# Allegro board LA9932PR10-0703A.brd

Outline 302.59 x 222.15 mm; copper layers: TOP, GND1, IN1, GND2, IN2, IN3, VCC, IN4, GND3, BOTTOM. Coordinates in mm from the lower left corner of the outline.

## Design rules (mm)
net group 12: nets PCH_PCIE_IREF PCH_PCIE_RCOMP
net group CLK-20: nets UIM_CLK UIM_DATA
net group CLK_BUF_BCLK: nets CLK_BUF_BCLK CLK_BUF_BCLK#
net group CLK_CPU_SSC_DPLL: nets CLK_CPU_SSC_DPLL CLK_CPU_SSC_DPLL#
net group CLK_KBD: nets CLK_KBD DAT_KBD
net group CLK_MSE: nets CLK_MSE DAT_MSE
net group CLK_PCIE_MINI1: nets CLK_PCIE_MINI1 CLK_PCIE_MINI1#
net group CLK_TP_SIO: nets CLK_TP_SIO DAT_TP_SIO
net group CPU_SSC_DPLL: nets CPU_SSC_DPLL CPU_SSC_DPLL#
net group CSS_1: nets CSSN_1 CSSP_1
net group DIFFPAIR75: nets M_CLK_DDR0 M_CLK_DDR#0
net group DIFFPAIR76: nets M_CLK_DDR2 M_CLK_DDR#2
net group DIFFPAIR145: nets DMIC0 DMIC_CLK
net group DIFFPAIR157: nets Z4304 Z4305
net group DOCK_DCIN_IS: nets DOCK_DCIN_IS+ DOCK_DCIN_IS-
net group DPC_CA_DET: nets DPC_CA_DET DPC_CA_DET#
net group DPC_DOCK_LANE_N0: nets DPC_DOCK_LANE_N0 DPC_DOCK_LANE_P0
net group DPC_DOCK_LANE_N1: nets DPC_DOCK_LANE_N1 DPC_DOCK_LANE_P1
net group DPC_DOCK_LANE_N2: nets DPC_DOCK_LANE_N2 DPC_DOCK_LANE_P2
net group DPC_DOCK_LANE_N3: nets DPC_DOCK_LANE_N3 DPC_DOCK_LANE_P3
net group DPD_CA_DET: nets DPD_CA_DET DPD_CA_DET#
net group DPD_DOCK_LANE_N0: nets DPD_DOCK_LANE_N0 DPD_DOCK_LANE_P0
net group DPD_DOCK_LANE_N1: nets DPD_DOCK_LANE_N1 DPD_DOCK_LANE_P1
net group DPD_DOCK_LANE_N2: nets DPD_DOCK_LANE_N2 DPD_DOCK_LANE_P2
net group DPD_DOCK_LANE_N3: nets DPD_DOCK_LANE_N3 DPD_DOCK_LANE_P3
net group FDI-SINGLE: nets FDI_CSYNC FDI_INT
net group ISUM: nets ISUMN ISUMP
net group PCH_DDPB_CTRLCLK: nets PCH_DDPB_CTRLCLK PCH_DDPB_CTRLDATA
net group PCIE_PRX_EXPTX_7: nets PCIE_PRX_EXPTX_N7 PCIE_PRX_EXPTX_P7
net group PCIE_PRX_GLANTX_2: nets PCIE_PRX_GLANTX_N2 PCIE_PRX_GLANTX_P2
net group PCIE_PRX_GLANTX_2_C: nets PCIE_PRX_GLANTX_N2_C PCIE_PRX_GLANTX_P2_C
net group PCIE_PRX_MMITX_8: nets PCIE_PRX_MMITX_N8 PCIE_PRX_MMITX_P8
net group PCIE_PRX_MMITX_8_C: nets PCIE_PRX_MMITX_N8_C PCIE_PRX_MMITX_P8_C
net group PCIE_PRX_WLANTX_3: nets PCIE_PRX_WLANTX_N3 PCIE_PRX_WLANTX_P3
net group PCIE_PRX_WPANTX_6: nets PCIE_PRX_WPANTX_N6 PCIE_PRX_WPANTX_P6
net group PCIE_PTX_EXPRX_7: nets PCIE_PTX_EXPRX_N7 PCIE_PTX_EXPRX_P7
net group PCIE_PTX_GLANRX_2: nets PCIE_PTX_GLANRX_N2 PCIE_PTX_GLANRX_P2
net group PCIE_PTX_GLANRX_2_C: nets PCIE_PTX_GLANRX_N2_C PCIE_PTX_GLANRX_P2_C
net group PCIE_PTX_MMIRX_8: nets PCIE_PTX_MMIRX_N8 PCIE_PTX_MMIRX_P8
net group PCIE_PTX_MMIRX_8_C: nets PCIE_PTX_MMIRX_N8_C PCIE_PTX_MMIRX_P8_C
net group PCIE_PTX_WLANRX_3: nets PCIE_PTX_WLANRX_N3 PCIE_PTX_WLANRX_P3
net group PCIE_PTX_WLANRX_3_C: nets PCIE_PTX_WLANRX_N3_C PCIE_PTX_WLANRX_P3_C
net group PCIE_PTX_WPANRX_6: nets PCIE_PTX_WPANRX_N6 PCIE_PTX_WPANRX_P6
net group PCIE_PTX_WPANRX_6_C: nets PCIE_PTX_WPANRX_N6_C PCIE_PTX_WPANRX_P6_C
net group PCIE_SATA_PRX_WANTX_4: nets PCIE_SATA_PRX_WANTX_N4 PCIE_SATA_PRX_WANTX_P4
net group PCIE_SATA_PTX_WANRX_4: nets PCIE_SATA_PTX_WANRX_N4 PCIE_SATA_PTX_WANRX_P4
net group PCIE_SATA_PTX_WANRX_4_C: nets PCIE_SATA_PTX_WANRX_N4_C PCIE_SATA_PTX_WANRX_P4_C
net group PECI-SINGLE: nets PECI_EC PECI_EC_R
net group PEG_CTX_GRX_0: nets PEG_CTX_GRX_N0 PEG_CTX_GRX_P0
net group PEG_CTX_GRX_2: nets PEG_CTX_GRX_N2 PEG_CTX_GRX_P2
net group PEG_CTX_GRX_4: nets PEG_CTX_GRX_N4 PEG_CTX_GRX_P4
net group PEG_CTX_GRX_6: nets PEG_CTX_GRX_N6 PEG_CTX_GRX_P6
net group PEG_CTX_GRX_C_0: nets PEG_CTX_GRX_C_N0 PEG_CTX_GRX_C_P0
net group PEG_CTX_GRX_C_2: nets PEG_CTX_GRX_C_N2 PEG_CTX_GRX_C_P2
net group PEG_CTX_GRX_C_4: nets PEG_CTX_GRX_C_N4 PEG_CTX_GRX_C_P4
net group PEG_CTX_GRX_C_6: nets PEG_CTX_GRX_C_N6 PEG_CTX_GRX_C_P6
net group PSATA_PRX_DTX_0_C: nets PSATA_PRX_DTX_N0_C PSATA_PRX_DTX_P0_C
net group PSATA_PTX_DRX_0_C: nets PSATA_PTX_DRX_N0_C PSATA_PTX_DRX_P0_C
net group RTCRST: nets PCH_RTCRST# SRTCRST#
net group SATA_PRX_DKTX_2: nets SATA_PRX_DKTX_N2 SATA_PRX_DKTX_P2
net group SATA_PRX_DKTX_2_C: nets SATA_PRX_DKTX_N2_C SATA_PRX_DKTX_P2_C
net group SATA_PTX_DKRX_2: nets SATA_PTX_DKRX_N2 SATA_PTX_DKRX_P2
net group SATA_PTX_DKRX_2_C: nets SATA_PTX_DKRX_N2_C SATA_PTX_DKRX_P2_C
net group TMDSB_CPU_CLK: nets TMDSB_CPU_CLK TMDSB_CPU_CLK#
net group TMDSB_CPU_N0: nets TMDSB_CPU_N0 TMDSB_CPU_P0
net group TMDSB_CPU_N1: nets TMDSB_CPU_N1 TMDSB_CPU_P1
net group TMDSB_CPU_N2: nets TMDSB_CPU_N2 TMDSB_CPU_P2
net group TMDSE_CPU_CLK_C: nets TMDSE_CPU_CLK#_C TMDSE_CPU_CLK_C
net group TMDSE_CPU_N0_C: nets TMDSE_CPU_N0_C TMDSE_CPU_P0_C
net group TMDSE_CPU_N1_C: nets TMDSE_CPU_N1_C TMDSE_CPU_P1_C
net group TMDSE_CPU_N2_C: nets TMDSE_CPU_N2_C TMDSE_CPU_P2_C
net group USB3R5: nets USB3RN5 USB3RP5
net group USB3R6: nets USB3RN6 USB3RP6
net group USB3RP5_D+: nets USB3RN5_D- USB3RP5_D+
net group USB3T5: nets USB3TN5 USB3TP5
net group USB3T5_C: nets USB3TN5_C USB3TP5_C
net group USB3T6: nets USB3TN6 USB3TP6
net group USB3TP5_D+: nets USB3TN5_D- USB3TP5_D+
net group USBP6_R_D: nets USBP6_R_D+ USBP6_R_D-
net group USBP13: nets USBP13+ USBP13-
net group USBP13_D: nets USBP13_D+ USBP13_D-
net group VSUM_VGA: nets VSUM+_VGA VSUM-_VGA
net group WCKA0_0: nets WCKA0_0 WCKA0B_0
net group WCKA0_1: nets WCKA0_1 WCKA0B_1
net group WCKA1_0: nets WCKA1_0 WCKA1B_0
net group WCKA1_1: nets WCKA1_1 WCKA1B_1
net group 10: nets PCH_SPI_CS0# PCH_SPI_CS1# PCH_SPI_DIN PCH_SPI_DO PCH_SPI_DO2 PCH_SPI_DO3 SPI_DIN32 SPI_DIN64 SPI_DO32 SPI_DO64 SPI_PCH_CLK SPI_PCH_CS0# SPI_PCH_CS0#_R SPI_PCH_CS1# SPI_PCH_CS1#_R SPI_PCH_DIN SPI_PCH_DO SPI_PCH_DO2 SPI_PCH_DO2_32 SPI_PCH_DO2_64 SPI_PCH_DO3 SPI_PCH_DO3_32 SPI_PCH_DO3_64
net group 15: nets CLK_80H CLK_PCH_14M CLK_PCI_LOOPBACK CLK_PCI_TPM CLK_SIO_14M EC_32KHZ_ECE5048 ICLK_IREF MEC_XTAL1 MEC_XTAL2 PCH_CLK_BIASREF PCI_LOOPBACKOUT PCI_TPM_TCM PCLK_80H PEG_COMP SIO_14M XTAL25_IN XTAL25_IN_R XTAL25_OUT XTALI XTALIN XTALO XTALOUT XTALOUT_R
net group 20: nets +NBDOCK_DC_IN_SS CFG_RCOMP CLK_PCI_5048 CLK_PCI_DOCK CLK_PCI_MEC DMI_IREF DMI_RCOMP FDI_IREF FDI_RCOMP PCH_SPI_CLK PCI_5048 PCI_DOCK PCI_MEC SATA_COMP SATA_IREF SPI_CLK32 SPI_CLK64
net group 25: nets EDP_COMP SM_RCOMP0 SM_RCOMP1 SM_RCOMP2
net group 30: nets CRT_IREF
net group ASYNCHRONOUS-50H: nets CPU_PLTRST# CPU_PLTRST#_R DDR3_DRAMRST#_CPU DDR3_DRAMRST#_R H_CATERR# H_CPUPWRGD H_CPUPWRGD_XDP H_PM_SYNC H_PROCHOT# H_PROCHOT#_R H_THERMTRIP# H_THERMTRIP#_R PCH_JTAG_TCK PCH_JTAG_TDI PCH_JTAG_TDO PCH_JTAG_TMS PCH_PLTRST# PCH_PLTRST#_BUF PCH_PLTRST#_EC PLTRST_EMB# PLTRST_GPU# PLTRST_LAN# PLTRST_MMI# PLTRST_USH# PM_DRAM_PWRGD PM_DRAM_PWRGD_CPU PM_DRAM_PWRGD_R PROCHOT#_EC RUNPWROK_AND THERMATRIP2# THERMATRIP3# VCCPWRGOOD_0_R XDP_PRDY# XDP_PREQ# XDP_RST#_R XDP_TCLK XDP_TDI XDP_TDI_R XDP_TDO XDP_TDO_R XDP_TMS XDP_TRST#
net group AUDIO: nets AUD_SENSE_A AUD_SENSE_B EXT_MIC RING2 RING2_L SLEEVE
net group BC BUS: nets BC_CLK_ECE1117 BC_CLK_ECE5048 BC_DAT_ECE1117 BC_DAT_ECE5048
net group CLK-15: nets DAI_12MHZ# DAI_BCLK# DMIC_CLK_L GPU_JTAG_TCK JTAG_CLK MSCLK MSDATA PS2_CLK_TS TP_CLK
net group CLK-HOST: nets CLK_BUF_CKSSCD CLK_BUF_CKSSCD# CLK_BUF_DMI CLK_BUF_DMI# CLK_BUF_DOT96 CLK_BUF_DOT96# CLK_CPU_DMI CLK_CPU_DMI# CLK_CPU_DPLL CLK_CPU_DPLL# CLK_PCIE_VGA CLK_PCIE_VGA# CPU_DMI CPU_DMI# CPU_DPLL CPU_DPLL#
net group CLK-SRC: nets CLK_PCIE_EMB CLK_PCIE_EMB# CLK_PCIE_EXP CLK_PCIE_EXP# CLK_PCIE_LAN CLK_PCIE_LAN# CLK_PCIE_MINI2 CLK_PCIE_MINI2# CLK_PCIE_MINI3 CLK_PCIE_MINI3# CLK_PCIE_MMI CLK_PCIE_MMI#
net group CONTROL LINK SIGNAL: nets PCH_CL_CLK1 PCH_CL_DATA1 PCH_CL_RST1#
net group CRITICAL TRACE: nets JTAG_TDI JTAG_TDO JTAG_TMS ME_RESET#
net group CRITICAL-SIGNALS: nets CFD_PWRBTN#_XDP DSWODVREN INTRUDER# PCH_DPWROK PCH_INTVRMEN PCH_PCIE_WAKE# PCH_PWRBTN#_XDP PCH_PWROK PCH_RSMRST# PCH_RSMRST#_Q PCH_RSMRST#_R PCH_THRMTRIP#_R PM_APWROK PM_APWROK_R RESET_OUT# RESET_OUT#_R SIO_PWRBTN# SIO_PWRBTN#_R SIO_RCIN# SIO_SLP_A# SYS_PWROK SYS_PWROK_R SYS_PWROK_XDP SYS_RESET# XDP_DBRESET#
net group CRT-DAC: nets BLUE_CRT BLUE_DOCK GREEN_CRT GREEN_DOCK PCH_CRT_BLU PCH_CRT_GRN PCH_CRT_RED RED_CRT RED_DOCK
net group CRT-SYNC: nets HSYNC HSYNC_BUF HSYNC_DOCK PCH_CRT_HSYNC PCH_CRT_VSYNC VSYNC VSYNC_BUF VSYNC_DOCK
net group DCIN_JACK: nets -DCIN_JACK
net group DDC-SIGNAL: nets CLK_DDC2_CRT CLK_DDC2_DOCK DAT_DDC2_CRT DAT_DDC2_DOCK HDMI_SCL_SINK HDMI_SDA_SINK PCH_CRT_DDC_CLK PCH_CRT_DDC_DAT
net group DDR-CLK: nets M_CLK_DDR1 M_CLK_DDR3 M_CLK_DDR#1 M_CLK_DDR#3
net group DDRA-CMD: nets DDR_A_BS0 DDR_A_BS1 DDR_A_BS2 DDR_A_CAS# DDR_A_MA0 DDR_A_MA1 DDR_A_MA2 DDR_A_MA3 DDR_A_MA4 DDR_A_MA5 DDR_A_MA6 DDR_A_MA7 DDR_A_MA8 DDR_A_MA9 DDR_A_MA10 DDR_A_MA11 DDR_A_MA12 DDR_A_MA13 DDR_A_MA14 DDR_A_MA15 DDR_A_RAS# DDR_A_WE#
net group DDRA-CTL: nets DDR_CKE0_DIMMA DDR_CKE1_DIMMA DDR_CS0_DIMMA# DDR_CS1_DIMMA# M_ODT0 M_ODT1
net group DDRB-CMD: nets DDR_B_BS0 DDR_B_BS1 DDR_B_BS2 DDR_B_CAS# DDR_B_MA0 DDR_B_MA1 DDR_B_MA2 DDR_B_MA3 DDR_B_MA4 DDR_B_MA5 DDR_B_MA6 DDR_B_MA7 DDR_B_MA8 DDR_B_MA9 DDR_B_MA10 DDR_B_MA11 DDR_B_MA12 DDR_B_MA13 DDR_B_MA14 DDR_B_MA15 DDR_B_RAS# DDR_B_WE#
net group DDRB-CTL: nets DDR_CKE2_DIMMB DDR_CKE3_DIMMB DDR_CS2_DIMMB# DDR_CS3_DIMMB# M_ODT2 M_ODT3
net group DDRD0_8_16_25: nets DDR_A_D8 DDR_A_D9 DDR_A_D10 DDR_A_D11 DDR_A_D12 DDR_A_D13 DDR_A_D14 DDR_A_D15 DDR_A_D24 DDR_A_D25 DDR_A_D26 DDR_A_D27 DDR_A_D28 DDR_A_D29 DDR_A_D30 DDR_A_D31 DDR_A_D40 DDR_A_D41 DDR_A_D42 DDR_A_D43 DDR_A_D44 DDR_A_D45 DDR_A_D46 DDR_A_D47 DDR_A_D56 DDR_A_D57 DDR_A_D58 DDR_A_D59 DDR_A_D60 DDR_A_D61 DDR_A_D62 DDR_A_D63 DDR_B_D8 DDR_B_D9 DDR_B_D10 DDR_B_D11 DDR_B_D12 DDR_B_D13 DDR_B_D14 DDR_B_D15 DDR_B_D24 DDR_B_D25 DDR_B_D26 DDR_B_D27 DDR_B_D28 DDR_B_D29 DDR_B_D30 DDR_B_D31 DDR_B_D40 DDR_B_D41 DDR_B_D42 DDR_B_D43 DDR_B_D44 DDR_B_D45 DDR_B_D46 DDR_B_D47 DDR_B_D56 DDR_B_D57 DDR_B_D58 DDR_B_D59 DDR_B_D60 DDR_B_D61 DDR_B_D62 DDR_B_D63
net group DDRD1_8_16_25: nets DDR_A_D0 DDR_A_D1 DDR_A_D2 DDR_A_D3 DDR_A_D4 DDR_A_D5 DDR_A_D6 DDR_A_D7 DDR_A_D16 DDR_A_D17 DDR_A_D18 DDR_A_D19 DDR_A_D20 DDR_A_D21 DDR_A_D22 DDR_A_D23 DDR_A_D32 DDR_A_D33 DDR_A_D34 DDR_A_D35 DDR_A_D36 DDR_A_D37 DDR_A_D38 DDR_A_D39 DDR_A_D48 DDR_A_D49 DDR_A_D50 DDR_A_D51 DDR_A_D52 DDR_A_D53 DDR_A_D54 DDR_A_D55 DDR_B_D0 DDR_B_D1 DDR_B_D2 DDR_B_D3 DDR_B_D4 DDR_B_D5 DDR_B_D6 DDR_B_D7 DDR_B_D16 DDR_B_D17 DDR_B_D18 DDR_B_D19 DDR_B_D20 DDR_B_D21 DDR_B_D22 DDR_B_D23 DDR_B_D32 DDR_B_D33 DDR_B_D34 DDR_B_D35 DDR_B_D36 DDR_B_D37 DDR_B_D38 DDR_B_D39 DDR_B_D48 DDR_B_D49 DDR_B_D50 DDR_B_D51 DDR_B_D52 DDR_B_D53 DDR_B_D54 DDR_B_D55
net group DDRS_16_25: nets DDR_A_DQS0 DDR_A_DQS1 DDR_A_DQS2 DDR_A_DQS3 DDR_A_DQS4 DDR_A_DQS5 DDR_A_DQS6 DDR_A_DQS7 DDR_A_DQS#0 DDR_A_DQS#1 DDR_A_DQS#2 DDR_A_DQS#3 DDR_A_DQS#4 DDR_A_DQS#5 DDR_A_DQS#6 DDR_A_DQS#7 DDR_B_DQS0 DDR_B_DQS1 DDR_B_DQS2 DDR_B_DQS3 DDR_B_DQS4 DDR_B_DQS5 DDR_B_DQS6 DDR_B_DQS7 DDR_B_DQS#0 DDR_B_DQS#1 DDR_B_DQS#2 DDR_B_DQS#3 DDR_B_DQS#4 DDR_B_DQS#5 DDR_B_DQS#6 DDR_B_DQS#7
net group DIFFPAIR43: nets DDR_XDP_WAN_SMBDAT_R2
net group DIFFPAIR60: nets GPU_JTAG_TDI
net group DIFFPAIR81: nets PS2_DAT_TS
net group DIFFPAIR104: nets TP_DATA
net group DMI: nets DMI_CRX_PTX_N0 DMI_CRX_PTX_N1 DMI_CRX_PTX_N2 DMI_CRX_PTX_N3 DMI_CRX_PTX_P0 DMI_CRX_PTX_P1 DMI_CRX_PTX_P2 DMI_CRX_PTX_P3 DMI_CTX_PRX_N0 DMI_CTX_PRX_N1 DMI_CTX_PRX_N2 DMI_CTX_PRX_N3 DMI_CTX_PRX_P0 DMI_CTX_PRX_P1 DMI_CTX_PRX_P2 DMI_CTX_PRX_P3
net group DP: nets DPC_CPU_LANE_N0 DPC_CPU_LANE_N0_C DPC_CPU_LANE_N1 DPC_CPU_LANE_N1_C DPC_CPU_LANE_N2 DPC_CPU_LANE_N2_C DPC_CPU_LANE_N3 DPC_CPU_LANE_N3_C DPC_CPU_LANE_P0 DPC_CPU_LANE_P0_C DPC_CPU_LANE_P1 DPC_CPU_LANE_P1_C DPC_CPU_LANE_P2 DPC_CPU_LANE_P2_C DPC_CPU_LANE_P3 DPC_CPU_LANE_P3_C DPC_DOCK_AUX DPC_DOCK_AUX# DPC_PCH_DOCK_AUX DPC_PCH_DOCK_AUX# DPC_PCH_DOCK_AUX#_C DPC_PCH_DOCK_AUX_C DPD_CPU_LANE_N0 DPD_CPU_LANE_N0_C DPD_CPU_LANE_N1 DPD_CPU_LANE_N1_C DPD_CPU_LANE_N2 DPD_CPU_LANE_N2_C DPD_CPU_LANE_N3 DPD_CPU_LANE_N3_C DPD_CPU_LANE_P0 DPD_CPU_LANE_P0_C DPD_CPU_LANE_P1 DPD_CPU_LANE_P1_C DPD_CPU_LANE_P2 DPD_CPU_LANE_P2_C DPD_CPU_LANE_P3 DPD_CPU_LANE_P3_C DPD_DOCK_AUX DPD_DOCK_AUX# DPD_PCH_DOCK_AUX DPD_PCH_DOCK_AUX# DPD_PCH_DOCK_AUX#_C DPD_PCH_DOCK_AUX_C
net group EDP: nets EDP_CPU_AUX EDP_CPU_AUX# EDP_CPU_AUX#_C EDP_CPU_AUX_C EDP_CPU_LANE_N0 EDP_CPU_LANE_N0_C EDP_CPU_LANE_N1 EDP_CPU_LANE_N1_C EDP_CPU_LANE_P0 EDP_CPU_LANE_P0_C EDP_CPU_LANE_P1 EDP_CPU_LANE_P1_C
net group ESD: nets CARD_RESET# CFG0 CFG1 CFG2 CFG3 CFG4 CFG5 CFG6 CFG7 CFG8 CFG9 CFG10 CFG11 CFG12 CFG13 CFG14 CFG15 CFG16 CFG17 CFG18 CFG19 CPUSB# DGPU_HOLD_RST# DOCK_POR_RST# DRAM_RST# DRAM_RST#_R EXPCLK_REQ# EXPRCRD_CPPE# IMVP_PWRGD IMVP_VR_ON JTAG_RST# ME_SUS_PWR_ACK ME_SUS_PWR_ACK_R POWER_SW#_MB POWER_SW_IN# RSMRST# RSMRST#_XDP RUNPWROK RUNPWROK_R SIO_EXT_SMI# SUSACK# SUSACK#_R USB_OC0# USB_OC1# USB_OC4# XDP_DBRESET#_R
net group FDI: nets FDI_CTX_PRX_N0 FDI_CTX_PRX_N1 FDI_CTX_PRX_P0 FDI_CTX_PRX_P1
net group HDA: nets PCH_AZ_BITCLK PCH_AZ_CODEC_BITCLK PCH_AZ_CODEC_RST# PCH_AZ_CODEC_SDIN0 PCH_AZ_CODEC_SDOUT PCH_AZ_CODEC_SYNC PCH_AZ_RST# PCH_AZ_SDIN0_R PCH_AZ_SDOUT PCH_AZ_SYNC
net group HDMI: nets TMDSE_CON_CLK TMDSE_CON_CLK# TMDSE_CON_N0 TMDSE_CON_N1 TMDSE_CON_N2 TMDSE_CON_P0 TMDSE_CON_P1 TMDSE_CON_P2 TMDSE_RP_CLK TMDSE_RP_CLK# TMDSE_RP_N0 TMDSE_RP_N1 TMDSE_RP_N2 TMDSE_RP_P0 TMDSE_RP_P1 TMDSE_RP_P2
net group HP: nets AUD_HP_OUT_L AUD_HP_OUT_L1 AUD_HP_OUT_L2 AUD_HP_OUT_R AUD_HP_OUT_R2
net group LAN: nets DOCK_LOM_TRD0+ DOCK_LOM_TRD0- DOCK_LOM_TRD1+ DOCK_LOM_TRD1- DOCK_LOM_TRD2+ DOCK_LOM_TRD2- DOCK_LOM_TRD3+ DOCK_LOM_TRD3- LAN_TX0+ LAN_TX0+R LAN_TX0- LAN_TX0-R LAN_TX1+ LAN_TX1+R LAN_TX1- LAN_TX1-R LAN_TX2+ LAN_TX2+R LAN_TX2- LAN_TX2-R LAN_TX3+ LAN_TX3+R LAN_TX3- LAN_TX3-R SW_LAN_TX0+ SW_LAN_TX0+_R SW_LAN_TX0- SW_LAN_TX0-_R SW_LAN_TX1+ SW_LAN_TX1+_R SW_LAN_TX1- SW_LAN_TX1-_R SW_LAN_TX2+ SW_LAN_TX2- SW_LAN_TX3+ SW_LAN_TX3-
net group LAN-NOREF: nets NB_LAN_TX0+ NB_LAN_TX0- NB_LAN_TX1+ NB_LAN_TX1- NB_LAN_TX2+ NB_LAN_TX2- NB_LAN_TX3+ NB_LAN_TX3-
net group LVDS: nets CVT_LVDS_A0+ CVT_LVDS_A0- CVT_LVDS_A1+ CVT_LVDS_A1- CVT_LVDS_A2+ CVT_LVDS_A2- CVT_LVDS_ACLK+ CVT_LVDS_ACLK- CVT_LVDS_B0+ CVT_LVDS_B0- CVT_LVDS_B1+ CVT_LVDS_B1- CVT_LVDS_B2+ CVT_LVDS_B2- CVT_LVDS_BCLK+ CVT_LVDS_BCLK- LCD_EDID_CLK LCD_EDID_DATA
net group OTHER-SINGLE: nets BAT1_LED# BAT1_LED#_Q BAT2_LED# BAT2_LED#_Q
net group PCIE: nets PCIE_PRX_EMBTX_N4 PCIE_PRX_EMBTX_P4 PCIE_PTX_EMBRX_N4 PCIE_PTX_EMBRX_N4_C PCIE_PTX_EMBRX_P4 PCIE_PTX_EMBRX_P4_C
net group PEG: nets PEG_CRX_GTX_C_N0 PEG_CRX_GTX_C_N1 PEG_CRX_GTX_C_N2 PEG_CRX_GTX_C_N3 PEG_CRX_GTX_C_N4 PEG_CRX_GTX_C_N5 PEG_CRX_GTX_C_N6 PEG_CRX_GTX_C_N7 PEG_CRX_GTX_C_P0 PEG_CRX_GTX_C_P1 PEG_CRX_GTX_C_P2 PEG_CRX_GTX_C_P3 PEG_CRX_GTX_C_P4 PEG_CRX_GTX_C_P5 PEG_CRX_GTX_C_P6 PEG_CRX_GTX_C_P7 PEG_CRX_GTX_N0 PEG_CRX_GTX_N1 PEG_CRX_GTX_N2 PEG_CRX_GTX_N3 PEG_CRX_GTX_N4 PEG_CRX_GTX_N5 PEG_CRX_GTX_N6 PEG_CRX_GTX_N7 PEG_CRX_GTX_P0 PEG_CRX_GTX_P1 PEG_CRX_GTX_P2 PEG_CRX_GTX_P3 PEG_CRX_GTX_P4 PEG_CRX_GTX_P5 PEG_CRX_GTX_P6 PEG_CRX_GTX_P7 PEG_CTX_GRX_C_N1 PEG_CTX_GRX_C_N3 PEG_CTX_GRX_C_N5 PEG_CTX_GRX_C_N7 PEG_CTX_GRX_C_P1 PEG_CTX_GRX_C_P3 PEG_CTX_GRX_C_P5 PEG_CTX_GRX_C_P7 PEG_CTX_GRX_N1 PEG_CTX_GRX_N3 PEG_CTX_GRX_N5 PEG_CTX_GRX_N7 PEG_CTX_GRX_P1 PEG_CTX_GRX_P3 PEG_CTX_GRX_P5 PEG_CTX_GRX_P7
net group POWER-20: nets +0.9V_LAN +0.675V_DDR_VTT +0.675V_P +1.2V_LDO +1.2V_LDO_OZ +1.2V_OZ_AUX_LDO +1.5V_CARD +1.05V_MP +1.5V_RUN +1.05V_RUN_CHG +1.5V_RUN_HDMI +1.5V_RUNP +1.05VSP_5V +1.05VSP_B+ +1.8V_MPLL_PVDD +1.8V_RUN_CARD +1.8V_RUN_FB +1.8V_RUN_GFX +1.8V_RUN_VIN +1.8V_RUNP +1.8V_SPLL_PVDD +1.35V_MEM_CHG +1.35V_MEM_GFX_CHG +1.35V_MEN_P +3.3V_ALW2 +3.3V_ALW_5048 +3.3V_ALW_PCH +3.3V_ALW_PCH_JTAG +3.3V_ALW_VTR +3.3V_CARD +3.3V_CARDAUX +3.3V_LAN +3.3V_LAN_OUT +3.3V_M +3.3V_OZ_IO_LDO +3.3V_PCIE_FLASH +3.3V_PCIE_WWAN +3.3V_RTC_LDO +3.3V_RUN_CARD +3.3V_RUN_DVDD +3.3V_RUN_EDP +3.3V_RUN_FFS +3.3V_RUN_GFX +3.3V_RUN_GFX_VDDR3 +3.3V_RUN_HDD +3.3V_RUN_HDD_R +3.3V_RUN_OZVCC +3.3V_RUN_TPM +3.3V_SPI +3.3V_SUS +3.3V_TP +3.3V_VCCPRTCSUS +3.3V_VTR +3.3V_VTR_ADC +3.3V_WLAN +3V5V_PWR_SRC +3VALWP +5V_ALW2 +5V_HDD +5V_MOD +5V_RUN +5V_TSP +5V_USB_CHG_PWR +5VALWP +ALC3226_CPVEE +ALC3226_LDO_CAP +ALC3226_VREF +AVCC33 +BATT_SUM +BL_PWR_SRC +CAMERA_VDD +CAP_LDO +COINCELL +DC_IN +DC_IN_SS +DCIN +DCIN_JACK +DDR_CHG +DIMM1_VREF_CA +DIMM1_VREF_DQ +DIMM2_VREF_CA +DIMM2_VREF_DQ +DVCC33 +DVDD_CORE +LCDVDD +LOM_VCT +PBATT +PBATT_C +PBATT_IN_SS +PCH_DCPRTC +PCH_VCC +PCH_VCCCFUSE +PCH_VCCCLK +PCH_VCCCLK3_3 +PCH_VCCDSW +PCH_VCCDSW3_3 +PCH_VCCDSW_R +PCH_VCCSST +PECI_VREF +PWR_SRC_AC +RSVD_VCC3P3_1 +RTC_CELL +RTC_CELL_VBAT +SA_DIMM1_VREFDQ +SA_DIMM_VREFDQ +SA_DIMM_VREFDQ_Q +SB_DIMM2_VREFDQ +SB_DIMM_VREFDQ +SB_DIMM_VREFDQ_Q +SDC_IN +SIM_PWR +SM_VREF +SM_VREF_DIMM +SM_VREF_Q +SW_LX +SWR_V12 +TRM_CT1 +TRM_CT2 +TRM_CT3 +TRM_CT4 +TSVDD +UIM_VPP +UTLGND +V_DDR_REF +VCCADAC +VCCIO2PCH +VCCIO2PCH_R +VCCIO_OUT +VCCST +VCHGR +VCOMP_OUT +VDD_MEM15_REFDA +VDD_MEM15_REFSA +VDDA_AVDD +VDDA_AVDD2 +VDDA_PVDD +VDDC_CT +VDISPLAY_VCC +VGA_B+ +VGA_PCIE_SPLL_VDDC +VGA_PCIEP +VR_CAP +VREFOUT
net group RTCX: nets PCH_RTCX1 PCH_RTCX1_R PCH_RTCX2
net group SATA3: nets SATA_ODD_PRX_DTX_N1 SATA_ODD_PRX_DTX_N1_C SATA_ODD_PRX_DTX_P1 SATA_ODD_PRX_DTX_P1_C SATA_ODD_PTX_DRX_N1 SATA_ODD_PTX_DRX_N1_C SATA_ODD_PTX_DRX_P1 SATA_ODD_PTX_DRX_P1_C SATA_PRX_DTX_N0 SATA_PRX_DTX_P0 SATA_PTX_DRX_N0 SATA_PTX_DRX_P0
net group SD: nets SD_D0_RCLK_P_MMC_D0 SD_D1_RCLK_N SD_D1_RCLKR_N SD_UHS2_D0N SD_UHS2_D0N_R SD_UHS2_D0P SD_UHS2_D0P_R SD_UHS2_D1N SD_UHS2_D1N_R SD_UHS2_D1P SD_UHS2_D1P_R
net group SD-CARD: nets SD_CD# SD_CLK SD_CLK_R SD_CMD SD_D2 SD_D3 SD_WPI
net group SD_D1_RCLKR_N: nets SD_D0_RCLKR_P
net group SENSE: nets VCCSENSE VCCSENSE_R VSSSENSE VSSSENSE_R
net group SMBUS: nets BAY_SMBCLK BAY_SMBDAT CARD_SMBCLK CARD_SMBDAT CHARGER_SMBCLK CHARGER_SMBDAT DDR_XDP_WAN_SMBCLK DDR_XDP_WAN_SMBCLK_R2 DDR_XDP_WAN_SMBDAT DOCK_SMB_CLK DOCK_SMB_DAT GPU_SMBCLK GPU_SMBDAT LAN_SMBCLK LAN_SMBCLK_R LAN_SMBDATA LAN_SMBDATA_R LCD_SMBCLK LCD_SMBDAT MEM_SMBCLK MEM_SMBDATA PBAT_SMBCLK PBAT_SMBDAT SML1_SMBCLK SML1_SMBDATA USH_SMBCLK USH_SMBDAT
net group SPK: nets INT_SPK_L+ INT_SPK_L- INT_SPK_R+ INT_SPK_R- INT_SPKL_L+ INT_SPKL_L- INT_SPKR_R+ INT_SPKR_R-
net group SVID: nets H_CPU_SVIDALRT# VIDALERT_N VIDSCLK VIDSOUT
net group THERMAL: nets REM_DIODE1_N REM_DIODE1_P REM_DIODE2_N REM_DIODE2_P REM_DIODE4_N REM_DIODE4_P VGA_THERMDN VGA_THERMDP
net group USB20: nets USBP0+ USBP0- USBP0_D+ USBP0_D- USBP0_R_D+ USBP0_R_D- USBP1+ USBP1- USBP1_D+ USBP1_D- USBP2+ USBP2- USBP2_D+ USBP2_D- USBP3+ USBP3- USBP4+ USBP4- USBP5+ USBP5- USBP6+ USBP6- USBP7+ USBP7- USBP8+ USBP8- USBP9+ USBP9- USBP10+ USBP10- USBP12+ USBP12- USBP12_D+ USBP12_D-
net group USB30: nets USB3RN1 USB3RN1_D- USB3RN2 USB3RN2_D- USB3RN3 USB3RP1 USB3RP1_D+ USB3RP2 USB3RP2_D+ USB3RP3 USB3TN1 USB3TN1_C USB3TN1_D- USB3TN2 USB3TN2_C USB3TN2_D- USB3TN3 USB3TP1 USB3TP1_C USB3TP1_D+ USB3TP2 USB3TP2_C USB3TP2_D+ USB3TP3
net group USB-SINGLE: nets USBRBIAS
net group VRAM-A_DBI: nets ADBIA0 ADBIA1 DDBIA0_0 DDBIA0_1 DDBIA0_2 DDBIA0_3 DDBIA1_0 DDBIA1_1 DDBIA1_2 DDBIA1_3
net group VRAM-CLK: nets CLKA0 CLKA0# CLKA1 CLKA1#
net group VRAM-CONTROL: nets CASA0# CASA1# CKEA0 CKEA1 CSA0#_0 CSA1#_0 RASA0# RASA1# WEA0# WEA1#
net group VRAM-DQ_A: nets DQA0_0 DQA0_1 DQA0_2 DQA0_3 DQA0_4 DQA0_5 DQA0_6 DQA0_7 DQA0_8 DQA0_9 DQA0_10 DQA0_11 DQA0_12 DQA0_13 DQA0_14 DQA0_15 DQA0_16 DQA0_17 DQA0_18 DQA0_19 DQA0_20 DQA0_21 DQA0_22 DQA0_23 DQA0_24 DQA0_25 DQA0_26 DQA0_27 DQA0_28 DQA0_29 DQA0_30 DQA0_31 DQA1_0 DQA1_1 DQA1_2 DQA1_3 DQA1_4 DQA1_5 DQA1_6 DQA1_7 DQA1_8 DQA1_9 DQA1_10 DQA1_11 DQA1_12 DQA1_13 DQA1_14 DQA1_15 DQA1_16 DQA1_17 DQA1_18 DQA1_19 DQA1_20 DQA1_21 DQA1_22 DQA1_23 DQA1_24 DQA1_25 DQA1_26 DQA1_27 DQA1_28 DQA1_29 DQA1_30 DQA1_31
net group VRAM-EDC: nets EDCA0_0 EDCA0_1 EDCA0_2 EDCA0_3 EDCA1_0 EDCA1_1 EDCA1_2 EDCA1_3
net group VRAM-MA_A: nets MAA0_0 MAA0_1 MAA0_2 MAA0_3 MAA0_4 MAA0_5 MAA0_6 MAA0_7 MAA0_8 MAA1_0 MAA1_1 MAA1_2 MAA1_3 MAA1_4 MAA1_5 MAA1_6 MAA1_7 MAA1_8
nets with their own width: min track width 0.508; nets +1.35V_MEM_GFX +GPU_CORE +VCC_CORE +VGA_PCIE GND GNDA_GPU_CORE Z2805 Z2806 Z2807 Z2808 Z4012
nets with their own width: min track width 1.016; nets +1.05V_M +DOCK_PWR_BAR GND_CHASSIS
nets with their own width: min track width 1.27; nets +1.05V_RUN
nets with their own width: min track width 1.524; nets +3.3V_RUN
nets with their own width: min track width 2.032; nets +5V_ALW +PWR_SRC
nets with their own width: min track width 2.159; nets +1.35V_MEM
nets with their own width: min track width 3.048; nets +3.3V_ALW

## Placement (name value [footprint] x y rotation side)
C7  -  [C_0805]  42.86 89.63 90 bottom
C8  -  [C_0402]  117.67 91.67 90 bottom
C9  -  [C_0402]  30.62 139.83 90 top
C16  -  [C_0402]  139.96 120.31 90 bottom
C18  -  [C_0402]  217.79 83.68 0 top
C25  -  [C_0402]  136.86 154.23 180 top
C26  -  [C_0402]  136.86 155.12 180 top
C27  -  [C_0402]  135.64 157.48 270 top
C28  -  [C_0402]  134.75 157.48 270 top
C29  -  [C_0402]  133.4 154.68 0 top
C30  -  [C_0402]  134.37 151.36 90 top
C31  -  [C_0402]  22.67 196.98 270 top
C32  -  [C_0402]  13.99 198.75 180 top
C44  -  [C_0402]  214.19 115.99 90 top
C45  -  [C_0402]  215.33 115.99 90 top
C46  -  [C_0402]  23.56 207.01 270 bottom
C47  -  [C_0603]  24.64 206.94 270 bottom
C50  -  [C_0402]  5.53 182.41 90 top
C51  -  [C_0402]  43.75 97.07 90 top
C52  -  [C_0402]  42.74 97.07 90 top
C53  -  [C_0402]  45.79 97.07 90 top
C100  -  [C_0402]  196.29 162.99 180 top
C101  -  [C_0402]  196.29 162.11 180 top
C103  -  [C_0402]  196.29 161.22 180 top
C104  -  [C_0402]  196.8 163.88 180 top
C105  -  [C_0402]  196.8 164.77 180 top
C106  -  [C_0603]  193.55 165.15 180 top
C107  -  [C_0402]  193.37 163.21 180 top
C108  -  [C_0402]  193.37 164.1 180 top
C109  -  [C_0603]  199.29 152.89 270 top
C110  -  [C_0402]  197.8 152.59 270 top
C111  -  [C_0402]  195.71 159.45 270 top
C112  -  [C_0402]  200.92 164.85 270 bottom
C113  -  [C_0603]  206.76 154.36 270 top
C114  -  [C_0402]  205.92 158.04 0 top
C115  -  [C_0603]  204.28 155.5 0 top
C116  -  [C_0402]  202.74 157.53 0 top
C117  -  [C_0402]  205.92 158.93 0 top
C118  -  [C_0402]  196.29 160.33 180 top
C246  -  [C_0603]  217.49 168.47 90 top
C247  -  [C_0603]  214.95 168.47 90 top
C283  -  [C_0402]  214.44 69.89 90 top
C284  -  [C_0402]  217.79 72.38 0 top
C285  -  [C_0402]  213.17 69.89 90 top
C286  -  [C_0402]  216.52 70.35 0 top
C287  -  [C_0402]  215.59 70.81 270 top
C288  -  [C_0402]  179.31 118.42 0 top
C289  -  [C_0402]  172.91 115 270 top
C290  -  [C_0402]  202.63 86.91 90 top
C296  -  [C_0603]  216.22 168.47 90 top
C297  -  [C_0402]  216.42 163.31 180 top
C298  -  [C_0402]  201.33 172.54 180 bottom
C299  -  [C_0402]  231.57 163.82 0 bottom
C300  -  [C_0603]  231.65 164.96 0 bottom
C301  -  [C_0402]  234.89 168.91 270 bottom
C302  -  [C_0402]  188.41 145.27 90 bottom
C306  -  [C_0402]  194.2 144.44 270 bottom
C340  -  [C_0402]  22.67 201.72 90 top
C342  -  [C_0402]  23.56 201.72 90 top
C344  -  [C_0402]  21.16 198.49 180 bottom
C346  -  [C_0402]  18.1 195.58 270 top
C347  -  [C_0402]  17.21 195.58 270 top
C348  -  [C_0402]  19.88 195.58 270 top
C349  -  [C_0402]  18.99 195.58 270 top
C350  -  [C_0402]  16.32 195.58 270 top
C351  -  [C_0402]  15.43 195.58 270 top
C352  -  [C_0402]  20.77 195.58 270 top
C353  -  [C_0402]  21.66 195.58 270 top
C354  -  [C_0402]  13.99 197.41 180 top
C355  -  [C_0402]  13.99 202.37 180 top
C356  -  [C_0402]  170.55 159.69 0 top
C357  -  [C_0402]  163.84 157.09 180 top
C360  -  [C_0402]  163.84 156.2 180 top
C365  -  [C_0402]  166 159.88 180 top
C366  -  [C_0402]  174.58 153.22 180 top
C367  -  [C_0402]  181.34 155.88 0 top
C368  -  [C_0402]  181.34 156.77 0 top
C369  -  [C_0402]  176.58 159.69 0 top
C383  -  [C_0402]  87.83 59.52 0 bottom
C384  -  [C_0402]  87.83 58.63 0 bottom
C385  -  [C_0402]  87.82 57.73 0 bottom
C386  -  [C_0402]  87.82 56.84 0 bottom
C387  -  [C_0603]  89.41 53.01 270 top
C388  -  [C_0402]  80.14 52.96 270 top
C395  -  [C_0402]  79.01 39.23 180 top
C396  -  [C_0402]  79.01 40.12 180 top
C397  -  [C_0402]  170.25 40.9 270 top
C398  -  [C_0402]  169.36 40.9 270 top
C399  -  [C_0402]  80.82 47.93 0 top
C402  -  [C_0402]  80.82 46.98 0 top
C404  -  [C_0402]  169.91 36.06 0 top
C405  -  [C_0402]  169.91 35.04 0 top
C406  -  [C_0402]  169.91 34.03 0 top
C407  -  [C_0402]  169.91 33.01 0 top
C408  -  [C_0402]  169.91 38.09 0 top
C409  -  [C_0402]  169.91 39.11 0 top
C416  -  [C_0402]  271.6 205.41 180 bottom
C417  -  [C_0402]  271.6 204.46 180 bottom
C418  -  [C_0402]  279.77 171.76 0 top
C419  -  [C_0402]  279.77 172.65 0 top
C423  -  [C_0603]  244.92 152.64 90 top
C435  -  [C_0402]  223.64 71.54 180 top
C436  -  [C_0402]  175.13 44.87 90 top
C437  -  [C_0402]  223.64 70.63 180 top
C438  -  [C_0402]  174.25 44.87 90 top
C439  -  [C_0603]  223.89 68.94 180 top
C443  -  [C_0603]  223.9 72.77 180 top
C444  -  [C_0402]  246.08 153.14 90 top
C445  -  [C_0402]  264.85 179.92 90 top
C446  -  [C_0603]  262 178.93 180 top
C447  -  [C_0603]  248.1 152.64 90 top
C448  -  [C_0402]  246.97 153.14 90 top
C449  -  [C_0603]  267.46 179.38 0 top
C450  -  [C_0402]  265.74 179.92 90 top
C451  -  [C_0402]  216.59 127.19 180 top
C452  -  [C_0603]  216.74 125.96 180 top
C453  -  [C_0603]  216.85 129.21 180 top
C454  -  [C_0402]  216.59 128.08 180 top
C455  -  [C_0603]  198.31 170.42 90 top
C458  -  [C_0402]  236.92 158.56 270 top
C459  -  [C_0402]  237.81 158.56 270 top
C460  -  [C_0402]  239.08 157.65 90 top
C461  -  [C_0402]  239.97 157.65 90 top
C462  -  [C_0603]  241.62 158.55 270 top
C463  -  [C_0402]  243.47 164.52 180 bottom
C464  -  [C_0603]  240.54 167.06 270 bottom
C466  -  [C_0402]  243.41 166.61 180 bottom
C467  -  [C_0402]  241.62 167.07 270 bottom
C468  -  [C_0402]  243.41 165.73 180 bottom
C469  -  [C_0402]  236.03 158.56 270 top
C470  -  [C_0402]  245.95 163.82 180 top
C471  -  [C_0402]  245.95 165.78 180 top
C472  -  [C_0402]  256.48 179.71 270 top
C473  -  [C_0402]  249.99 183.44 0 top
C474  -  [C_0402]  244.1 179.64 270 top
C478  -  [C_0402]  260.54 174.69 270 top
C479  -  [C_0603]  262.07 189.73 0 top
C480  -  [C_0603]  262.07 191 0 top
C481  -  [C_0603]  243.91 182.55 0 bottom
C482  -  [C_0402]  243.84 206.31 270 top
C483  -  [C_0603]  262.07 197.54 0 top
C484  -  [C_0603]  262.07 198.81 0 top
C485  -  [C_1808]  245.29 200.84 0 bottom
C500  -  [C_0402]  261.67 187.62 90 top
C501  -  [C_0402]  261.67 192.75 90 top
C550  -  [C_0402]  214.62 103.75 0 top
C551  -  [C_0402]  211.27 115.99 90 top
C552  -  [C_0402]  211.27 104.71 270 top
C553  -  [C_0402]  214.62 104.64 0 top
C559  -  [C_0603]  188.3 19.62 180 top
C560  -  [C_0603]  191.45 20.63 180 top
C561  -  [C_0603]  191.73 32.45 270 top
C564  -  [C_0603]  179.77 19.6 0 top
C566  -  [C_0603]  193.11 22.79 180 top
C567  -  [C_0402]  178.36 27.87 0 top
C568  -  [C_0402]  178.36 28.76 0 top
C569  -  [C_0402]  178.36 26.98 0 top
C571  -  [C_0402]  178.36 26.09 0 top
C572  -  [C_0603]  206.62 31.71 0 top
C574  -  [C_0402]  188.36 21.88 0 top
C575  -  [C_0402]  193.42 24.77 270 top
C576  -  [C_0402]  181.36 25 90 top
C577  -  [C_0603]  180.28 24.5 90 top
C578  -  [C_0603]  177.97 22.94 180 top
C580  -  [C_0402]  190.3 19.55 0 top
C581  -  [C_0402]  186.63 31.85 90 top
C595  -  [C_0402]  197.82 147.4 270 bottom
C596  -  [C_0402]  207.51 160.39 0 bottom
C598  -  [C_0402]  207.51 161.28 0 bottom
C603  -  [C_0402]  192.66 149.23 270 bottom
C604  -  [C_0402]  204.8 147.44 180 bottom
C605  -  [C_0402]  213.91 159.95 0 bottom
C606  -  [C_0402]  216.09 149.55 270 top
C607  -  [C_0402]  214.82 160.84 180 bottom
C608  -  [C_0603]  193.61 148.45 0 bottom
C610  -  [C_0402]  281.62 191.58 270 bottom
C611  -  [C_0402]  258.32 191.65 270 bottom
C612  -  [C_0402]  276.29 204.47 90 bottom
C613  -  [C_0805]  270.74 191.15 0 bottom
C614  -  [C_0402]  277.18 204.47 90 bottom
C615  -  [C_D2]  262.87 184.08 0 top
C616  -  [C_0402]  223.88 155.26 270 top
C617  -  [C_0402]  290.06 168.01 180 bottom
C618  -  [C_0402]  290.06 167.12 180 bottom
C621  -  [C_0402]  277.45 185.47 180 top
C622  -  [C_0402]  286.2 165.8 270 top
C623  -  [C_0402]  285.31 165.86 270 top
C624  -  [C_0402]  278.02 173.47 180 top
C625  -  [C_0402]  277.1 162.8 0 top
C626  -  [C_0603]  278.32 163.88 180 top
C628  -  [C_0402]  225.9 155.26 270 top
C629  -  [C_0402]  228.55 155.26 270 top
C630  -  [C_0402]  226.98 155.25 270 top
C631  -  [C_0402]  224.98 155.26 270 top
C633  -  [C_0402]  237.95 64.47 90 top
C634  -  [C_0402]  234.63 66.97 90 top
C635  -  [C_0402]  234.89 59.12 270 top
C636  -  [C_0402]  222.99 155.26 270 top
C637  -  [C_0402]  233.49 59.12 270 top
C638  -  [C_0603]  232.41 58.92 180 top
C639  -  [C_0603]  221.85 155.25 270 top
C640  -  [C_0402]  233.68 66.91 90 top
C641  -  [C_0603]  232.6 66.67 90 top
C642  -  [C_0402]  235.9 59.12 270 top
C643  -  [C_0603]  236.98 59.05 270 top
C645  -  [C_0402]  223.28 33.14 180 top
C646  -  [C_0402]  223.28 34.03 180 top
C649  -  [C_0402]  223.28 36.69 180 top
C651  -  [C_APXK6R3ARA221MF451]  284.7 199.83 90 top
C654  -  [C_0402]  285.04 197.25 270 top
C675  -  [C_0402]  282.27 190.81 180 top
C676  -  [C_0603]  282.45 189.73 180 top
C679  -  [C_0402]  120.46 155.99 270 bottom
C680  -  [C_0402]  120.5 167.2 90 top
C681  -  [C_0402]  121.35 155.99 270 bottom
C682  -  [C_0402]  121.39 167.2 90 top
C683  -  [C_0402]  122.24 155.99 270 bottom
C684  -  [C_0402]  122.28 167.2 90 top
C685  -  [C_0402]  124.02 155.99 270 bottom
C686  -  [C_0402]  124.06 167.2 90 top
C687  -  [C_0402]  124.91 155.99 270 bottom
C688  -  [C_0402]  124.94 167.2 90 top
C689  -  [C_0402]  125.79 155.99 270 bottom
C690  -  [C_0402]  119.57 155.99 270 bottom
C691  -  [C_0402]  119.61 167.2 90 top
C692  -  [C_0402]  123.13 155.99 270 bottom
C693  -  [C_0402]  123.17 167.2 90 top
C694  -  [C_0402]  125.83 167.2 90 top
C695  -  [C_0402]  127.07 161.74 270 top
C696  -  [C_0402]  127.45 169.87 270 top
C697  -  [C_0402]  132.12 165.12 90 top
C698  -  [C_0402]  133.01 165.12 90 top
C699  -  [C_0402]  133.9 166.03 270 top
C700  -  [C_0402]  134.79 166.03 270 top
C701  -  [C_0402]  148.46 168.82 90 top
C702  -  [C_0603]  154.32 161.23 180 top
C703  -  [C_0603]  109.92 162.23 180 top
C705  -  [C_0603]  184.15 77.21 180 top
C706  -  [C_0402]  184.93 76.13 180 top
C707  -  [C_0402]  184.85 59.38 270 top
C708  -  [C_0402]  193.54 66.03 0 top
C709  -  [C_0402]  191.52 75.86 90 top
C710  -  [C_0402]  177.94 66.16 180 top
C714  -  [C_0603]  178.18 67.3 180 top
C715  -  [C_0402]  276.29 183.43 90 top
C716  -  [C_0402]  182.82 59.38 270 top
C720  -  [C_0402]  198.62 88.13 0 top
C721  -  [C_0402]  202.63 69.89 90 top
C722  -  [C_0402]  204.66 70.81 270 top
C724  -  [C_0402]  202.76 74.49 270 top
C725  -  [C_0402]  214.19 157.01 90 top
C727  -  [C_0402]  211.14 154.5 270 top
C733  -  [C_0402]  202.71 68.38 180 top
C734  -  [C_0402]  202.71 67.43 180 top
C735  -  [C_0402]  197.85 84.45 0 top
C736  -  [C_0402]  201.44 78.35 180 top
C737  -  [C_0402]  217.79 74.41 0 top
C739  -  [C_0402]  217.79 77.21 0 top
C740  -  [C_0402]  201.44 85.08 180 top
C741  -  [C_0402]  200.52 74.29 0 top
C742  -  [C_0402]  209.49 70.81 270 top
C743  -  [C_0402]  201.44 76.32 180 top
C744  -  [C_0402]  210.57 66.61 270 top
C746  -  [C_0402]  226.07 127.88 180 top
C755  -  [C_0402]  188.93 100.65 180 top
C756  -  [C_0402]  199.65 98.62 270 top
C757  -  [C_0402]  201.44 79.37 180 top
C758  -  [C_0402]  198.63 98.62 270 top
C759  -  [C_0402]  218.71 68.95 180 top
C764  -  [C_0603]  177.1 43.61 270 top
C765  -  [C_0603]  171.77 41.46 270 top
C772  -  [C_0603]  163.39 113.97 0 top
C773  -  [C_0402]  156.06 111.05 180 top
C774  -  [C_0402]  211.77 70.81 270 top
C775  -  [C_0402]  217.79 78.1 0 top
C776  -  [C_0402]  209.74 86.91 90 top
C777  -  [C_0402]  217.79 79.49 0 top
C778  -  [C_0402]  228.3 114.09 90 top
C779  -  [C_0603]  212.54 68.25 270 top
C780  -  [C_0402]  214.36 85.72 0 top
C781  -  [C_0402]  201.44 83.3 180 top
C782  -  [C_0603]  218.7 67.81 180 top
C783  -  [C_0603]  84.39 89.26 180 top
C800  -  [C_0402]  192.61 21.71 180 top
C802  -  [C_0402]  202.87 31.89 270 top
C952  -  [C_0603]  267.84 156.45 0 bottom
C954  -  [C_0603]  265.56 160.65 90 top
C955  -  [C_0603]  277.75 153.66 0 top
C956  -  [C_0603]  280.23 160.2 270 top
C957  -  [C_0402]  277.74 154.8 0 top
C958  -  [C_0805]  275.01 162.92 90 top
C959  -  [C_0402]  270.13 163.87 90 top
C960  -  [C_0805]  268.59 164.52 90 top
C961  -  [C_0402]  273.67 162.92 90 top
C962  -  [C_0603]  277.81 160.2 270 top
C963  -  [C_0603]  274 151.88 270 top
C965  -  [C_0603]  279.55 157.62 180 top
C967  -  [C_0603]  266.83 163.31 180 top
C968  -  [C_0402]  279.08 160.21 270 top
C969  -  [C_0603]  278.16 156.23 0 top
C972  -  [C_0402]  280.87 152.01 270 bottom
C973  -  [C_0402]  178.77 14.28 180 top
C974  -  [C_0402]  179.82 14.28 0 top
C975  -  [C_0402]  182.58 14.28 180 top
C976  -  [C_0402]  183.76 14.28 0 top
C977  -  [C_0402]  263.91 156.95 90 top
C994  -  [C_0402]  265.7 157.98 180 top
C998  -  [C_0402]  6.54 182.41 90 top
C1001  -  [C_0402]  6.68 180.52 180 top
C1002  -  [C_0402]  15.14 145.58 90 top
C1004  -  [C_0402]  257.44 153 0 top
C1105  -  [C_0402]  264.4 152.9 0 top
C1106  -  [C_0402]  264.4 153.79 0 top
C1107  -  [C_0402]  277.74 152.45 0 top
C1167  -  [C_0402]  267.59 206.4 270 bottom
C1177  -  [C_0805]  237.24 169.76 90 top
C1178  -  [C_0805]  248.79 160.56 90 top
C1184  -  [C_0402]  229.19 114.09 90 top
C1214  -  [C_0603]  277.73 151.12 0 top
C1216  -  [C_0402]  226.07 121.02 180 top
C1247  -  [C_0603]  282.01 152.01 270 bottom
C1501  -  [C_0402]  181.17 21.44 90 top
C1502  -  [C_0603]  179.06 21.3 90 top
C1503  -  [C_0402]  182.74 21.4 0 top
C1504  -  [C_0603]  182.23 19.59 0 top
C1505  -  [C_0402]  189.26 32.03 180 top
C1506  -  [C_0402]  180.07 23.55 0 top
C1507  -  [C_0603]  187.89 35.16 270 top
C1508  -  [C_0402]  180.58 30.37 0 top
C1509  -  [C_0402]  192.64 27.52 180 top
C1510  -  [C_0402]  192.48 30.06 180 top
C1518  -  [C_0402]  286.39 188.95 90 top
C1519  -  [C_0402]  287.28 188.95 90 top
C1523  -  [C_B2]  291.65 185.74 180 bottom
C1524  -  [C_0402]  289.85 186.48 180 bottom
C1525  -  [C_0603]  280.54 179.89 270 top
C1526  -  [C_0402]  280.75 180.84 180 top
C1533  -  [C_0402]  279.08 186.03 90 top
C1534  -  [C_0402]  279.97 186.03 90 top
C1538  -  [C_B2]  286.13 170.4 90 top
C1539  -  [C_0402]  282.21 170.68 180 top
C1540  -  [C_0603]  277.62 167.31 180 top
C1541  -  [C_0402]  277.64 168.39 180 top
C1551  -  [C_0402]  154.94 156.89 90 bottom
C1552  -  [C_0805]  283.57 204.84 0 bottom
C1553  -  [C_0402]  105.69 110.4 0 top
C1554  -  [C_0402]  162.12 119.4 0 bottom
C1555  -  [C_0402]  55.74 91.46 0 bottom
C1556  -  [C_0402]  285.66 154.47 90 top
C1557  -  [C_0402]  285.89 157.83 270 top
C1558  -  [C_0402]  262.09 171.85 0 top
C1559  -  [C_0402]  261.28 150.4 90 top
CC1  -  [C_0402]  89.33 146.68 0 bottom
CC2  -  [C_0402]  89.33 145.79 0 bottom
CC3  -  [C_0402]  91.37 145.53 0 bottom
CC4  -  [C_0402]  91.37 144.64 0 bottom
CC5  -  [C_0402]  89.33 144.33 0 bottom
CC6  -  [C_0402]  89.33 143.44 0 bottom
CC7  -  [C_0402]  91.3 143.12 0 bottom
CC8  -  [C_0402]  91.3 142.23 0 bottom
CC9  -  [C_0402]  93.08 141.79 0 bottom
CC10  -  [C_0402]  93.08 140.9 0 bottom
CC11  -  [C_0402]  90.6 132.71 0 bottom
CC12  -  [C_0402]  90.6 131.82 0 bottom
CC13  -  [C_0402]  87.68 132.33 0 bottom
CC14  -  [C_0402]  87.68 131.44 0 bottom
CC15  -  [C_0402]  90.54 130.42 0 bottom
CC16  -  [C_0402]  90.54 129.53 0 bottom
CC17  -  [C_0402]  98.48 80.76 0 bottom
CC18  -  [C_0402]  98.48 79.87 0 bottom
CC19  -  [C_0402]  103.07 52 180 top
CC21  -  [C_0402]  103.03 94.4 180 bottom
CC24  -  [C_0805]  120.08 88.04 90 bottom
CC25  -  [C_0805]  121.98 88.04 90 bottom
CC26  -  [C_0805]  123.89 88.04 90 bottom
CC27  -  [C_0805]  127.7 88.04 90 bottom
CC28  -  [C_0805]  125.79 88.04 90 bottom
CC29  -  [C_0805]  133.41 88.04 90 bottom
CC30  -  [C_0805]  131.51 88.04 90 bottom
CC31  -  [C_0805]  129.6 88.04 90 bottom
CC32  -  [C_0805]  121.98 88.04 90 top
CC33  -  [C_0805]  123.89 88.04 90 top
CC34  -  [C_D2]  128.55 58.93 270 top
CC35  -  [C_D2]  133.38 58.93 270 top
CC36  -  [C_0805]  118.17 88.04 90 bottom
CC37  -  [C_0805]  135.32 88.04 90 bottom
CC38  -  [C_0805]  137.22 88.04 90 bottom
CC39  -  [C_0805]  137.22 88.04 90 top
CC40  -  [C_0805]  135.32 88.04 90 top
CC41  -  [C_0805]  129.6 88.04 90 top
CC42  -  [C_0805]  133.41 88.04 90 top
CC43  -  [C_0805]  125.79 88.04 90 top
CC44  -  [C_0805]  127.7 88.04 90 top
CC45  -  [C_0805]  131.51 88.04 90 top
CC46  -  [C_0805]  120.08 88.04 90 top
CC47  -  [C_0805]  103.79 111.88 180 top
CC48  -  [C_0805]  103.79 113.59 180 top
CC137  -  [C_0603]  151.07 96.45 180 bottom
CC138  -  [C_0402]  107.56 47.62 0 top
CD1  -  [C_0402]  91.75 34.98 0 top
CD2  -  [C_0402]  91.75 35.87 0 top
CD3  -  [C_0402]  118.75 27.56 270 top
CD4  -  [C_0402]  125.48 36.2 270 top
CD5  -  [C_0402]  124.33 36.2 270 top
CD6  -  [C_0402]  118.75 36.26 270 top
CD7  -  [C_0603]  117.29 36.88 270 top
CD8  -  [C_0603]  121.48 36.57 270 top
CD9  -  [C_0603]  124.27 27.87 270 top
CD10  -  [C_0603]  126.11 28.06 270 top
CD11  -  [C_0603]  120.27 28.12 270 top
CD12  -  [C_0603]  116.27 28.63 270 top
CD13  -  [C_0603]  128.91 36.44 270 top
CD14  -  [C_APXK2R5ARA331MF451]  131.26 33.17 90 top
CD15  -  [C_0402]  135.94 23.8 0 top
CD16  -  [C_0402]  135.94 22.91 0 top
CD17  -  [C_0402]  154.45 33.84 180 top
CD18  -  [C_0402]  154.45 36.5 180 top
CD19  -  [C_0402]  154.45 34.72 180 top
CD20  -  [C_0402]  154.45 35.61 180 top
CD21  -  [C_0402]  154.45 38.28 180 top
CD22  -  [C_0402]  154.45 37.39 180 top
CD23  -  [C_0402]  91.9 23.1 180 top
CD24  -  [C_0402]  91.9 22.22 180 top
CD25  -  [C_0402]  117.73 22.48 270 top
CD26  -  [C_0402]  125.86 22.61 270 top
CD27  -  [C_0402]  122.87 14.29 270 top
CD28  -  [C_0402]  121.92 22.42 270 top
CD29  -  [C_0603]  130.62 22.72 270 top
CD30  -  [C_0603]  123.64 22.91 270 top
CD31  -  [C_0603]  116.33 22.91 270 top
CD32  -  [C_0603]  128.65 14.6 270 top
CD33  -  [C_0603]  126.24 14.66 270 top
CD34  -  [C_0603]  118.94 14.66 270 top
CD35  -  [C_0603]  116.24 14.62 270 top
CD36  -  [C_APXK2R5ARA331MF451]  112.52 33.69 0 top
CD37  -  [C_0402]  131.5 13.77 0 top
CD38  -  [C_0402]  131.5 14.66 0 top
CD39  -  [C_0402]  154.48 21.99 180 top
CD40  -  [C_0402]  154.48 22.87 180 top
CD41  -  [C_0402]  154.48 23.76 180 top
CD42  -  [C_0402]  154.48 29.11 180 top
CD43  -  [C_0402]  151.77 22.14 90 top
CD44  -  [C_0402]  150.88 22.14 90 top
CD45  -  [C_0402]  97.46 24.63 0 top
CD46  -  [C_0402]  90.37 24.56 180 top
CD47  -  [C_0402]  94.29 26.91 0 top
CD48  -  [C_0402]  100.92 23.74 180 top
CE5  -  [C_0402]  22.55 206.44 270 top
CE6  -  [C_0805]  111.76 170.97 90 top
CE7  -  [C_0402]  25.21 206.44 270 top
CE10  -  [C_0402]  230.77 61.97 180 top
CE11  -  [C_0402]  230.77 60.95 180 top
CE12  -  [C_0402]  230.77 62.98 180 top
CE13  -  [C_0402]  15.43 206.44 270 top
CE14  -  [C_0402]  21.66 206.44 270 top
CE15  -  [C_0402]  18.99 206.44 270 top
CE16  -  [C_0402]  14.54 206.44 270 top
CE17  -  [C_0402]  11.88 206.44 270 top
CE18  -  [C_0402]  18.1 206.44 270 top
CH2  -  [C_0402]  203.28 100.03 180 bottom
CH4  -  [C_0402]  184.42 125.53 180 top
CH5  -  [C_0402]  180.85 123.29 90 top
CH6  -  [C_0402]  180.62 128.83 180 top
CH7  -  [C_0402]  177.92 128.83 0 top
CH10  -  [C_0402]  164.87 133.36 0 top
CH11  -  [C_0402]  179.01 124.53 270 bottom
CH12  -  [C_0402]  163.25 118.48 0 top
CH13  -  [C_0402]  161.3 154.61 180 bottom
CH14  -  [C_0402]  158.61 154.61 0 bottom
CH17  -  [C_0402]  157.8 124.34 270 bottom
CH18  -  [C_0402]  170.39 147.88 180 top
CH19  -  [C_0402]  170.39 148.77 180 top
CH20  -  [C_0603]  170.25 149.85 180 top
CH21  -  [C_0603]  158.69 136.58 180 top
CH22  -  [C_0402]  165.92 136.32 0 top
CH23  -  [C_0402]  163.31 134.87 0 top
CH24  -  [C_0402]  163.17 136.32 0 top
CH25  -  [C_0402]  165.08 134.86 0 top
CH27  -  [C_0402]  162.94 140.38 90 top
CH28  -  [C_0805]  167.73 117.83 270 top
CH29  -  [C_0402]  170.39 136.32 180 top
CH30  -  [C_0402]  168.59 134.86 0 top
CH34  -  [C_0402]  164.99 138.04 180 top
CH35  -  [C_0402]  162.63 137.26 90 top
CH36  -  [C_0402]  161.76 137.28 180 top
CH37  -  [C_0402]  161.22 142.69 0 top
CH38  -  [C_0603]  157.68 135.5 270 top
CH40  -  [C_0402]  176 131.51 270 top
CH43  -  [C_0402]  167.98 137.98 180 top
CH44  -  [C_0402]  179.83 135.04 90 bottom
CH45  -  [C_0402]  168.61 136.33 180 top
CH46  -  [C_0402]  166.63 133.29 270 top
CH47  -  [C_0402]  168.68 139.56 180 top
CH48  -  [C_0402]  169.54 139.56 0 top
CH49  -  [C_0402]  171.53 137.21 180 top
CH50  -  [C_0402]  168.47 146.09 90 top
CH51  -  [C_0402]  163.85 146.2 180 top
CH52  -  [C_0603]  152.66 134.55 0 top
CH53  -  [C_0402]  181.74 127.96 270 top
CH54  -  [C_0402]  169.77 133.32 180 top
CH55  -  [C_0402]  179.07 129.58 270 bottom
CH56  -  [C_0402]  179.96 129.58 270 bottom
CH57  -  [C_0402]  180.85 129.58 270 bottom
CH59  -  [C_0402]  166.51 129.9 90 top
CH60  -  [C_0402]  163.85 127.69 180 top
CH61  -  [C_0402]  163.85 128.58 180 top
CH62  -  [C_0402]  164.72 127.68 90 top
CH63  -  [C_0603]  157.77 150.9 180 bottom
CH64  -  [C_0402]  158.82 150.29 90 bottom
CH65  -  [C_0402]  163.25 116.96 0 bottom
CH66  -  [C_0402]  180.28 137.39 90 top
CH67  -  [C_0402]  164.78 147.06 0 top
CH68  -  [C_0402]  164.78 146.17 0 top
CH69  -  [C_0402]  165.73 141.15 0 top
CH70  -  [C_0402]  166.38 142.15 90 top
CH71  -  [C_0402]  166.9 139.63 180 top
CH72  -  [C_0402]  170.52 138.1 180 top
CH73  -  [C_0402]  169.75 141.3 0 top
CH74  -  [C_0402]  175.14 139.89 270 top
CH75  -  [C_0402]  168.85 141.16 180 top
CH76  -  [C_0402]  177.29 146.85 90 top
CMOS1  -  [SHORTPADS]  178.13 129.91 0 top
CV1  -  [C_0402]  86.54 145.6 0 top
CV2  -  [C_0402]  86.54 144.71 0 top
CV3  -  [C_0402]  89.72 144.84 0 top
CV4  -  [C_0402]  89.72 145.72 0 top
CV5  -  [C_0402]  85.97 143.12 0 top
CV6  -  [C_0402]  85.97 142.23 0 top
CV7  -  [C_0402]  89.72 143.44 0 top
CV8  -  [C_0402]  89.72 142.55 0 top
CV9  -  [C_0402]  90.35 131.56 0 top
CV10  -  [C_0402]  90.35 130.67 0 top
CV11  -  [C_0402]  87.43 131.06 0 top
CV12  -  [C_0402]  87.43 130.17 0 top
CV13  -  [C_0402]  81.73 118.18 270 top
CV14  -  [C_0402]  93.91 130.67 0 top
CV15  -  [C_0402]  93.91 129.79 0 top
CV16  -  [C_0402]  93.91 128.9 0 top
CV17  -  [C_0402]  93.91 128.01 0 top
CV18  -  [C_0402]  83.38 118.18 270 top
CV19  -  [C_0402]  72.33 118.18 270 top
CV20  -  [C_0402]  85.98 118.18 270 top
CV21  -  [C_0402]  84.27 118.18 270 top
CV22  -  [C_0402]  67.12 129.48 270 top
CV23  -  [C_0402]  74.91 129.7 90 top
CV24  -  [C_0402]  68.43 128.91 270 top
CV25  -  [C_0402]  67.19 127.45 270 top
CV26  -  [C_0402]  80.84 118.18 270 top
CV41  -  [C_0603]  91.95 96.83 270 top
CV42  -  [C_0603]  81.85 94.23 270 top
CV43  -  [C_0603]  55.57 97.27 270 top
CV44  -  [C_0603]  65.28 94.29 270 top
CV49  -  [C_0402]  72.96 138.43 270 top
CV52  -  [C_0402]  91.75 123.05 0 top
CV53  -  [C_0402]  89.27 117.02 0 top
CV54  -  [C_0402]  75.62 139.25 0 top
CV55  -  [C_0402]  76 138.36 0 top
CV56  -  [C_0603]  86.93 117.4 0 top
CV57  -  [C_0402]  91.53 116.14 90 top
CV58  -  [C_0603]  86.93 118.61 0 top
CV59  -  [C_0603]  86.93 119.82 0 top
CV60  -  [C_0603]  76.33 140.39 0 top
CV61  -  [C_0402]  65.04 142.1 180 top
CV62  -  [C_0402]  71.69 138.43 270 top
CV66  -  [C_0603]  80.97 146.11 90 top
CV67  -  [C_0402]  79.95 145.17 270 top
CV68  -  [C_0402]  80.84 145.17 270 top
CV69  -  [C_0402]  82.04 131.36 90 top
CV70  -  [C_0603]  86.81 128.26 270 top
CV71  -  [C_0402]  81.16 131.36 90 top
CV72  -  [C_0603]  88.01 128.26 270 top
CV73  -  [C_0402]  75.87 132.33 0 top
CV74  -  [C_0402]  75.87 133.53 0 top
CV75  -  [C_0402]  75.94 134.8 0 top
CV76  -  [C_0402]  78.06 129.98 180 top
CV77  -  [C_0402]  83.57 131.3 90 top
CV78  -  [C_0402]  68 137.74 0 top
CV79  -  [C_0402]  68.91 136.58 180 top
CV80  -  [C_0402]  70.88 136.58 180 top
CV81  -  [C_0402]  69.9 137.79 0 top
CV82  -  [C_0402]  69.97 135.44 0 top
CV83  -  [C_0402]  72.79 136.58 180 top
CV84  -  [C_0603]  67.67 138.78 0 top
CV85  -  [C_0402]  58.49 136.21 270 top
CV86  -  [C_0402]  59.81 135.56 0 top
CV87  -  [C_0402]  83.68 150.11 0 top
CV92  -  [C_0402]  71.24 144.82 0 top
CV93  -  [C_0402]  71.24 146.17 0 top
CV94  -  [C_0402]  79.19 150.79 90 bottom
CV95  -  [C_0402]  80.14 149.16 270 bottom
CV98  -  [C_0603]  71 147.25 0 top
CV129  -  [C_0402]  85.54 86.3 270 top
CV130  -  [C_0402]  91.75 96.96 0 bottom
CV131  -  [C_0402]  91.75 97.85 0 bottom
CV133  -  [C_0402]  68.14 94.37 270 bottom
CV134  -  [C_0402]  69.03 94.37 270 bottom
CV137  -  [C_0402]  87.95 94.3 270 bottom
CV138  -  [C_0402]  91.75 104.96 0 bottom
CV139  -  [C_0402]  91.75 105.85 0 bottom
CV140  -  [C_0402]  88.84 94.3 270 bottom
CV141  -  [C_0402]  79 94.3 270 top
CV142  -  [C_0402]  88.84 94.3 270 top
CV143  -  [C_0402]  87.95 94.3 270 top
CV144  -  [C_0402]  69.92 94.37 270 top
CV145  -  [C_0402]  68.14 94.37 270 top
CV146  -  [C_0402]  69.03 94.37 270 top
CV147  -  [C_0402]  71.69 94.37 270 bottom
CV148  -  [C_0402]  70.81 94.37 270 bottom
CV149  -  [C_0402]  69.92 94.37 270 bottom
CV150  -  [C_0402]  72.58 94.37 270 bottom
CV151  -  [C_0402]  87.06 94.3 270 top
CV152  -  [C_0402]  91.75 99.62 0 top
CV153  -  [C_0402]  91.75 100.51 0 top
CV154  -  [C_0402]  91.75 98.73 0 bottom
CV155  -  [C_0402]  91.75 99.62 0 bottom
CV156  -  [C_0402]  70.81 94.37 270 top
CV157  -  [C_0402]  55.7 100 180 top
CV158  -  [C_0402]  55.77 105.72 180 top
CV159  -  [C_0402]  67.25 94.37 270 bottom
CV162  -  [C_0402]  66.36 94.37 270 bottom
CV163  -  [C_0402]  73.22 118.18 270 top
CV164  -  [C_0402]  75.19 118.18 270 top
CV165  -  [C_0402]  76.08 118.18 270 top
CV166  -  [C_0402]  78.04 118.18 270 top
CV167  -  [C_0402]  78.93 118.18 270 top
CV176  -  [C_0402]  91.75 97.85 0 top
CV177  -  [C_0402]  91.75 98.73 0 top
CV178  -  [C_0402]  80.77 94.3 270 top
CV179  -  [C_0402]  91.75 96.07 0 bottom
CV180  -  [C_0402]  66.36 94.37 270 top
CV181  -  [C_0402]  58.55 111.42 90 bottom
CV182  -  [C_0402]  87.06 94.3 270 bottom
CV185  -  [C_0402]  57.66 111.42 90 bottom
CV188  -  [C_0402]  79.89 94.3 270 top
CV189  -  [C_0402]  67.25 94.37 270 top
CV191  -  [C_0402]  55.7 98.23 180 top
CV192  -  [C_0402]  55.7 99.12 180 top
CV198  -  [C_0402]  69.46 144.84 0 top
CV199  -  [C_0402]  67.9 145.72 180 top
CV201  -  [C_0603]  69.92 148.07 180 top
CV202  -  [C_0603]  67.88 146.8 180 top
CV203  -  [C_0402]  69.46 146.17 0 top
CV204  -  [C_0402]  67.9 144.84 180 top
CV207  -  [C_0402]  83.49 111.43 0 top
CV208  -  [C_0402]  91.76 103.17 90 top
CV209  -  [C_0402]  64.21 93.4 180 top
CV210  -  [C_0402]  62.44 93.4 180 top
CV215  -  [C_0402]  61.6 131.26 270 top
CV216  -  [C_0603]  58.37 131.09 180 top
CV219  -  [C_0402]  60.71 131.26 270 top
CV220  -  [C_0402]  61.6 128.57 90 top
CV221  -  [C_0603]  58.3 129.09 270 top
CV222  -  [C_0402]  60.71 128.57 90 top
CV223  -  [C_0402]  61.6 126.79 90 top
CV224  -  [C_0603]  59.63 126.61 90 top
CV225  -  [C_0402]  60.71 126.79 90 top
CV274  -  [C_0603]  81.93 127.69 270 top
CV275  -  [C_0603]  81.35 129.02 90 top
CV322  -  [C_0402]  81.71 111.43 0 top
CV323  -  [C_0402]  82.92 94.29 0 top
CV324  -  [C_0402]  84.7 94.29 0 top
CV325  -  [C_0402]  82.92 94.29 0 bottom
CV326  -  [C_0402]  91.76 104.94 90 top
CV327  -  [C_0402]  84.7 94.29 0 bottom
CV328  -  [C_0402]  92.53 103.17 270 bottom
CV329  -  [C_0402]  92.53 101.41 270 bottom
CV330  -  [C_0402]  87.96 111.43 180 top
CV331  -  [C_0402]  86.18 111.43 180 top
CV332  -  [C_0402]  63.95 112.31 90 top
CV333  -  [C_0402]  66.63 113.21 180 top
CV340  -  [C_0402]  73.47 143.87 90 top
CV341  -  [C_0402]  72.14 147.23 90 bottom
CV342  -  [C_0402]  70.23 147.23 90 bottom
CV343  -  [C_0402]  58.5 125.85 180 top
CV344  -  [C_0402]  62.47 125.91 0 top
CV349  -  [C_0402]  55.69 103.93 90 top
CV350  -  [C_0402]  53.91 102.15 90 top
CV351  -  [C_0402]  62.23 111.36 90 bottom
CV352  -  [C_0402]  59.55 111.37 0 bottom
CV353  -  [C_0402]  56.71 106.17 270 bottom
CV354  -  [C_0402]  56.77 109.73 270 bottom
CV355  -  [C_0402]  62.44 94.29 180 bottom
CV356  -  [C_0402]  64.21 94.29 180 bottom
CV357  -  [C_0402]  68.07 147.23 90 bottom
CV358  -  [C_0402]  60.98 133.15 180 top
CV411  -  [C_0402]  94.24 117.14 90 top
CV423  -  [C_0603]  93.16 117.21 90 top
D1  -  [RB751V40_SC76-2]  48.21 95.47 0 bottom
D7  -  [BAT54CW_SOT323-3]  191.84 172.62 0 top
D9  -  [BAT54CW_SOT323-3]  214.1 152.71 270 top
D10  -  [BAT54CW_SOT323-3]  217.14 161.6 270 top
D31  -  [RB751V40_SC76-2]  199.95 145.21 90 bottom
D32  -  [RB751V40_SC76-2]  152.75 154.56 0 bottom
D33  -  [L30ESD24VC3-2_SOT23-3]  107.55 171.19 270 top
D35  -  [RB751V40_SC76-2]  210.46 150.61 180 top
D36  -  [RB751V40_SC76-2]  217.57 154.61 180 top
D59  -  [RB751V40_SC76-2]  223.96 109.08 180 top
D62  -  [RB751V40_SC76-2]  223.96 107.43 180 top
D71  -  [RB751V40_SC76-2]  90.47 127.06 0 top
D72  -  [L30ESDL5V0C3-2_SOT23-3]  274.58 192.74 180 top
D78  -  [TVWDF1004AD0_DFN9]  279.3 192.52 180 top
D81  -  [L03ESDL5V0CC3-2_SOT23-3]  285.66 160.26 270 top
D82  -  [L03ESDL5V0CC3-2_SOT23-3]  285.66 152.01 270 top
D86  -  [PESD5V0U2BT_SOT23-3]  191.85 141.55 270 bottom
D88  -  [TVWDF1004AD0_DFN9]  285.2 194.29 0 top
D89  -  [L30ESDL5V0C3-2_SOT23-3]  287.49 185.54 90 top
D90  -  [L30ESDL5V0C3-2_SOT23-3]  284.33 177.09 270 top
D91  -  [TVWDF1004AD0_DFN9]  285.33 174.28 270 top
FD1  -  [FIDUCIAL_C40M80]  192.6 10.53 0 top
FD2  -  [FIDUCIAL_C40M80]  11.05 204.72 180 bottom
FD3  -  [FIDUCIAL_C40M80]  2.73 198.75 0 top
FD4  -  [FIDUCIAL_C40M80]  220.41 4.12 180 bottom
H1  -  [H_3P8]  3.89 169.85 0 top
H2  -  [H_3P8]  3.89 193.15 0 top
H3  -  [H_3P3]  102.15 105.7 0 top
H4  -  [H_3P0]  167.59 15.85 0 top
H5  -  [H_3P3]  102.15 76 0 top
H6  -  [H_3P3]  152.65 105.7 0 top
H7  -  [H_3P0]  183.39 167.72 0 top
H8  -  [H_3P0]  80.09 83.35 0 top
H9  -  [H_3P3]  152.65 76 0 top
H10  -  [H_3P0]  80.09 18.78 0 top
H11  -  [H_3P0]  89.79 167.72 0 top
H12  -  [H_3P0]  234.59 150.85 0 top
H13  -  [H_3P0]  293.49 208.3 0 top
H14  -  [H_3P2]  257.71 161.85 0 top
H15  -  [H_3P3]  90.19 137.15 0 top
H16  -  [H_3P3]  49.34 146.2 0 top
H17  -  [H_2P0N]  85.79 168.9 0 top
H18  -  [H_2P3]  227.79 23.15 0 top
H19  -  [H_2P3]  227.79 44.15 0 top
H20  -  [H_3P0]  296.59 152.45 0 top
H21  -  [H_3P1X2P1N]  288.94 208.3 0 top
H22  -  [H_3P3]  250.59 86.75 0 top
H23  -  [H_3P3]  59.79 117.05 0 top
JAPS1  -  [TYCO_1-2041070-6_16P]  232.22 93.4 270 top
